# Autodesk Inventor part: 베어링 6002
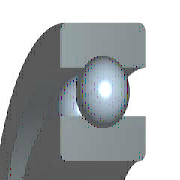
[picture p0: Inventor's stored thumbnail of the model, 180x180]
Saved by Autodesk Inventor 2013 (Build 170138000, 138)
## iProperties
IsCustomPart: 0
Created: 2015-10
Part Number: 베어링 6002
Material: 강철, 연강
Description: 깊은 그루브 볼 베어링
Document SubType Name: Modeling
Standard: KS B 2023
Designer: mdu
Standards Organization: KS
Language: ko-KR
Size Designation: 6002 - 15 x 32 x 9
Categories: <MemberInstance><Categories><Category DisplayName="샤프트 부품" InternalName="7f7aeb1f-a693-4053-b835-cee3144e0d98" Mnemonic="SHFT"><Category DisplayName="베어링" Inter
Density: 7.86 g/cm^3
Mass: 29.8124 g
Surface Area: 39.9079 cm^2
Volume: 3.79293 cm^3
Author: mdu
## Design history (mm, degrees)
sketch "스케치" dims "d0" = 4.42 (= -0.26 x WD + 0.26 x BD)
  geometry: L1 (2.29, 11.75)-(6.71, 11.75); L2 (4.5, 11.75)-(4.5, 9.54); L3 (4.5, 11.75)-(4.5, 13.96); L4 (2.858, 10.271)-(0, 10.271); L5 (0, 7.5)-(9, 7.5); L6 (2.858, 13.229)-(0, 13.229); L7 (0, 16)-(9, 16); L8 (9, 7.5)-(9, 10.271); L9 (6.142, 10.271)-(9, 10.271); L10 (6.142, 13.229)-(9, 13.229); L11 (9, 16)-(9, 13.229); L12 (-1.4, 0)-(8.4, 0) reference; L13 (0, -0.3)-(0, 5.3) reference
  constraints: 22 end point, 4 point on line, 2 collinear, 2 perpendicular, 2 symmetric about line, 1 midpoint, 1 parallel, 14 other
  dimensions: "d9" = 15 diameter of L5 L12 (= WD); "d11" = 32 diameter of L7 L12 (= BD); "d12" = 9 distance between parallel lines of L8 L13 (= KB); "d13" = 20.542 diameter of L9 L12 (= 0.326 x BD + 0.674 x WD)
revolve "본체" stored, may be unused: angle "d6" = 90 deg
revolve "볼" stored, may be unused: angle "d7" = 90 deg
pattern_circular "IDS_ARRAYBALL[SIMPL:T]" dims angle "d3" = 360 deg
body "Solid1"
fillet "모깎기1" dims "d1" = 0.3 (= KRS)
other parameters: "WD" = 15 [user parameter; used in 5 equation terms], "BD" = 32 [user parameter; used in 5 equation terms], "KB" = 9 [user parameter; used in 1 equation term], "KRS" = 0.3 [user parameter; used in 1 equation term], "d4" = 0, "d5" = 0, "d8" = 0, "d14" = 0, "d15" = 0, "BBA" = 0 [user parameter], "BC0" = 2850000 [user parameter], "BC" = 5590000 [user parameter], "BR" = 16 (= 0.5 x BD) [user parameter], "WR" = 7.5 (= 0.5 x WD) [user parameter]
